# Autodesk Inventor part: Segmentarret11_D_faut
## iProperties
Created: 2011-10
Part Number: Segmentarret11_D_faut
Document SubType Name: Modeling
Designer: Bruno
Author: Bruno
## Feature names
1. Base1
